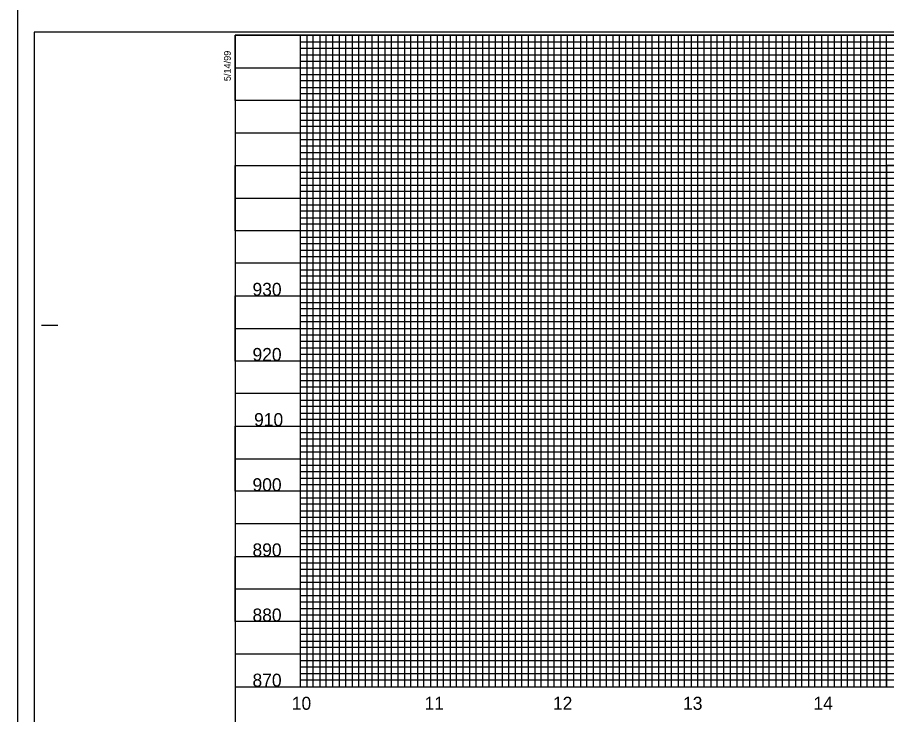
# Model space of a CAD drawing. Extents: x 1967929 to 1975641, y 546296 to 568534.
# Drawn here: x 1969864 to 1970531, y 565787 to 566323 of the extents above; entities that cross this region are included whole.
import ezdxf

# ---------------------------------------------------------------- set-up
doc = ezdxf.new("R2010")
doc.units = 0
for name, color, linetype in [('Exist Vertical Profile Horizontal Axis Label Major', 7, 'Continuous'), ('Exist Vertical Profile Vertical Axis Label', 7, 'Continuous'), ('Old_Level_41', 7, 'Continuous'), ('Scratch_Level_3', 7, 'Continuous'), ('Sheet Cutting Line CELL', 7, 'Continuous'), ('Sheet Plot Border Inside CELL', 7, 'Continuous'), ('Sheet Plot Border Outside CELL', 7, 'Continuous'), ('Sheet Profile CELL', 7, 'Continuous'), ('Sheet Profile Grid Major CELL', 7, 'Continuous'), ('Sheet Profile Grid Middle CELL', 7, 'Continuous'), ('Sheet Profile Grid Minor CELL', 7, 'Continuous')]:
    doc.layers.add(name, color=color, linetype=linetype)

msp = doc.modelspace()

# ---------------------------------------------------------------- linework, layer by layer
at = {"layer": 'Old_Level_41'}
msp.add_line((1969882.95, 566086.36), (1969895.45, 566086.36), dxfattribs=at)
at = {"layer": 'Scratch_Level_3'}
for points in [[(1970031.45, 565808.86), (1970781.45, 565808.86), (1970781.45, 566308.86), (1970031.45, 566308.86)], [(1970081.45, 566308.86), (1970081.45, 565808.86), (1971481.45, 565808.86), (1971481.45, 566112.51), (1971331.4, 566112.51), (1971331.4, 566308.86)], [(1970081.45, 566308.86), (1970081.45, 565808.86), (1971331.45, 565808.86), (1971331.45, 566077.21), (1971331.45, 566077.21), (1971331.45, 566308.86)], [(1970531.45, 566208.86), (1970531.45, 565808.86), (1971931.45, 565808.86), (1971931.45, 566112.51), (1971781.45, 566112.51), (1971781.45, 566208.86)]]:
    msp.add_lwpolyline(points, close=True, dxfattribs=at)
at = {"layer": 'Sheet Cutting Line CELL'}
msp.add_line((1969864.45, 566333.86), (1969864.45, 565233.86), dxfattribs=at)
at = {"layer": 'Sheet Plot Border Inside CELL'}
msp.add_lwpolyline([(1969877.45, 565256.31), (1971543.95, 565256.31), (1971543.95, 566311.41), (1969877.45, 566311.41)], close=True, dxfattribs=at)
at = {"layer": 'Sheet Plot Border Outside CELL'}
msp.add_lwpolyline([(1969864.45, 565233.86), (1971548.45, 565233.86), (1971548.45, 566333.86), (1969864.45, 566333.86)], close=True, dxfattribs=at)
at = {"layer": 'Sheet Profile CELL'}
msp.add_line((1970031.45, 565808.86), (1971531.45, 565808.86), dxfattribs=at)
msp.add_lwpolyline([(1971531.45, 566308.86), (1970031.45, 566308.86), (1970031.45, 565258.86), (1971531.45, 565258.86)], close=True, dxfattribs=at)
at = {"layer": 'Sheet Profile Grid Major CELL'}
for p, q in [((1970031.45, 566158.86), (1970031.45, 566208.86)), ((1970031.45, 566208.86), (1970681.45, 566208.86)), ((1970681.45, 566158.86), (1970031.45, 566158.86)), ((1970031.45, 566058.86), (1970031.45, 566108.86)), ((1970031.45, 566108.86), (1970681.45, 566108.86)), ((1970681.45, 566058.86), (1970031.45, 566058.86)), ((1970031.45, 565958.86), (1970031.45, 566008.86)), ((1970031.45, 566008.86), (1970681.45, 566008.86)), ((1970681.45, 565958.86), (1970031.45, 565958.86)), ((1970031.45, 565858.86), (1970031.45, 565908.86)), ((1970031.45, 565908.86), (1970681.45, 565908.86)), ((1970681.45, 565858.86), (1970031.45, 565858.86))]:
    msp.add_line(p, q, dxfattribs=at)
for points in [[(1970681.45, 566258.86), (1970031.45, 566258.86), (1970031.45, 566308.86), (1971331.45, 566308.86)], [(1970081.45, 566308.86), (1970081.45, 565808.86), (1970131.45, 565808.86), (1970131.45, 566308.86)], [(1970181.45, 566308.86), (1970181.45, 565808.86), (1970231.45, 565808.86), (1970231.45, 566308.86)], [(1970281.45, 566308.86), (1970281.45, 565808.86), (1970331.45, 565808.86), (1970331.45, 566308.86)], [(1970381.45, 566308.86), (1970381.45, 565808.86), (1970431.45, 565808.86), (1970431.45, 566308.86)], [(1970481.45, 566308.86), (1970481.45, 565808.86), (1970531.45, 565808.86), (1970531.45, 566308.86)]]:
    msp.add_lwpolyline(points, dxfattribs=at)
at = {"layer": 'Sheet Profile Grid Middle CELL'}
for p, q in [((1970031.45, 566233.86), (1970031.45, 566183.86)), ((1970681.45, 566233.86), (1970031.45, 566233.86)), ((1970031.45, 566183.86), (1970681.45, 566183.86)), ((1970031.45, 566133.86), (1970031.45, 566083.86)), ((1970681.45, 566133.86), (1970031.45, 566133.86)), ((1970031.45, 566083.86), (1970681.45, 566083.86)), ((1970031.45, 566033.86), (1970031.45, 565983.86)), ((1970681.45, 566033.86), (1970031.45, 566033.86)), ((1970031.45, 565983.86), (1970681.45, 565983.86)), ((1970031.45, 565933.86), (1970031.45, 565883.86)), ((1970681.45, 565933.86), (1970031.45, 565933.86)), ((1970031.45, 565883.86), (1970681.45, 565883.86))]:
    msp.add_line(p, q, dxfattribs=at)
for points in [[(1970031.45, 566308.86), (1970031.45, 566283.86), (1970681.45, 566283.86)], [(1970106.45, 565808.86), (1970106.45, 566308.86)], [(1970156.45, 566308.86), (1970156.45, 565808.86), (1970206.45, 565808.86), (1970206.45, 566308.86)], [(1970256.45, 566308.86), (1970256.45, 565808.86), (1970306.45, 565808.86), (1970306.45, 566308.86)], [(1970356.45, 566308.86), (1970356.45, 565808.86), (1970406.45, 565808.86), (1970406.45, 566308.86)], [(1970456.45, 566308.86), (1970456.45, 565808.86), (1970506.45, 565808.86), (1970506.45, 566308.86)], [(1970681.45, 565833.86), (1970031.45, 565833.86)]]:
    msp.add_lwpolyline(points, dxfattribs=at)
at = {"layer": 'Sheet Profile Grid Minor CELL'}
for p, q in [((1970081.45, 566248.86), (1970081.45, 566243.86)), ((1970681.45, 566248.86), (1970081.45, 566248.86)), ((1970081.45, 566243.86), (1970681.45, 566243.86)), ((1970681.45, 566238.86), (1970081.45, 566238.86)), ((1970081.45, 566238.86), (1970081.45, 566228.86)), ((1970081.45, 566228.86), (1970681.45, 566228.86)), ((1970681.45, 566223.86), (1970081.45, 566223.86)), ((1970081.45, 566223.86), (1970081.45, 566218.86)), ((1970081.45, 566218.86), (1970681.45, 566218.86)), ((1970681.45, 566213.86), (1970081.45, 566213.86)), ((1970081.45, 566213.86), (1970081.45, 566203.86)), ((1970081.45, 566203.86), (1970681.45, 566203.86)), ((1970681.45, 566198.86), (1970081.45, 566198.86)), ((1970081.45, 566198.86), (1970081.45, 566193.86)), ((1970081.45, 566193.86), (1970681.45, 566193.86)), ((1970681.45, 566188.86), (1970081.45, 566188.86)), ((1970081.45, 566188.86), (1970081.45, 566178.86)), ((1970081.45, 566178.86), (1970681.45, 566178.86)), ((1970681.45, 566173.86), (1970081.45, 566173.86)), ((1970081.45, 566173.86), (1970081.45, 566168.86)), ((1970081.45, 566168.86), (1970681.45, 566168.86)), ((1970681.45, 566163.86), (1970081.45, 566163.86)), ((1970081.45, 566163.86), (1970081.45, 566153.86)), ((1970081.45, 566153.86), (1970681.45, 566153.86)), ((1970081.45, 566148.86), (1970081.45, 566143.86)), ((1970681.45, 566148.86), (1970081.45, 566148.86)), ((1970081.45, 566143.86), (1970681.45, 566143.86)), ((1970081.45, 566138.86), (1970081.45, 566128.86)), ((1970681.45, 566138.86), (1970081.45, 566138.86)), ((1970081.45, 566128.86), (1970681.45, 566128.86)), ((1970081.45, 566123.86), (1970081.45, 566118.86)), ((1970681.45, 566123.86), (1970081.45, 566123.86)), ((1970081.45, 566118.86), (1970681.45, 566118.86)), ((1970681.45, 566113.86), (1970081.45, 566113.86)), ((1970081.45, 566113.86), (1970081.45, 566103.86)), ((1970081.45, 566103.86), (1970681.45, 566103.86)), ((1970681.45, 566098.86), (1970081.45, 566098.86)), ((1970081.45, 566098.86), (1970081.45, 566093.86)), ((1970081.45, 566093.86), (1970681.45, 566093.86)), ((1970681.45, 566088.86), (1970081.45, 566088.86)), ((1970081.45, 566088.86), (1970081.45, 566078.86)), ((1970081.45, 566078.86), (1970681.45, 566078.86)), ((1970681.45, 566073.86), (1970081.45, 566073.86)), ((1970081.45, 566073.86), (1970081.45, 566068.86)), ((1970081.45, 566068.86), (1970681.45, 566068.86)), ((1970681.45, 566063.86), (1970081.45, 566063.86)), ((1970081.45, 566063.86), (1970081.45, 566053.86)), ((1970081.45, 566053.86), (1970681.45, 566053.86)), ((1970681.45, 566048.86), (1970081.45, 566048.86)), ((1970081.45, 566048.86), (1970081.45, 566043.86)), ((1970081.45, 566043.86), (1970681.45, 566043.86)), ((1970681.45, 566038.86), (1970081.45, 566038.86)), ((1970081.45, 566038.86), (1970081.45, 566028.86)), ((1970081.45, 566028.86), (1970681.45, 566028.86)), ((1970681.45, 566023.86), (1970081.45, 566023.86)), ((1970081.45, 566023.86), (1970081.45, 566018.86)), ((1970081.45, 566018.86), (1970681.45, 566018.86)), ((1970681.45, 566013.86), (1970081.45, 566013.86)), ((1970081.45, 566003.86), (1970681.45, 566003.86)), ((1970681.45, 565998.86), (1970081.45, 565998.86)), ((1970081.45, 565998.86), (1970081.45, 565993.86)), ((1970081.45, 565993.86), (1970681.45, 565993.86)), ((1970681.45, 565988.86), (1970081.45, 565988.86)), ((1970081.45, 565978.86), (1970681.45, 565978.86)), ((1970681.45, 565973.86), (1970081.45, 565973.86)), ((1970081.45, 565973.86), (1970081.45, 565968.86)), ((1970081.45, 565968.86), (1970681.45, 565968.86)), ((1970681.45, 565963.86), (1970081.45, 565963.86)), ((1970081.45, 565963.86), (1970081.45, 565953.86)), ((1970081.45, 565953.86), (1970681.45, 565953.86)), ((1970681.45, 565948.86), (1970081.45, 565948.86)), ((1970081.45, 565948.86), (1970081.45, 565943.86)), ((1970081.45, 565943.86), (1970681.45, 565943.86)), ((1970681.45, 565938.86), (1970081.45, 565938.86)), ((1970081.45, 565938.86), (1970081.45, 565928.86)), ((1970081.45, 565928.86), (1970681.45, 565928.86)), ((1970681.45, 565923.86), (1970081.45, 565923.86)), ((1970081.45, 565923.86), (1970081.45, 565918.86)), ((1970081.45, 565918.86), (1970681.45, 565918.86)), ((1970681.45, 565913.86), (1970081.45, 565913.86)), ((1970081.45, 565913.86), (1970081.45, 565903.86)), ((1970081.45, 565903.86), (1970681.45, 565903.86)), ((1970681.45, 565898.86), (1970081.45, 565898.86)), ((1970081.45, 565898.86), (1970081.45, 565893.86)), ((1970081.45, 565893.86), (1970681.45, 565893.86)), ((1970681.45, 565888.86), (1970081.45, 565888.86)), ((1970081.45, 565888.86), (1970081.45, 565878.86)), ((1970081.45, 565878.86), (1970681.45, 565878.86)), ((1970081.45, 565873.86), (1970081.45, 565868.86)), ((1970681.45, 565873.86), (1970081.45, 565873.86)), ((1970081.45, 565868.86), (1970681.45, 565868.86)), ((1970681.45, 565863.86), (1970081.45, 565863.86)), ((1970081.45, 565863.86), (1970081.45, 565853.86)), ((1970081.45, 565853.86), (1970681.45, 565853.86)), ((1970681.45, 565848.86), (1970081.45, 565848.86)), ((1970081.45, 565848.86), (1970081.45, 565843.86)), ((1970081.45, 565843.86), (1970681.45, 565843.86)), ((1970681.45, 565838.86), (1970081.45, 565838.86)), ((1970081.45, 565838.86), (1970081.45, 565828.86)), ((1970081.45, 565828.86), (1970681.45, 565828.86)), ((1970081.45, 565823.86), (1970081.45, 565818.86)), ((1970681.45, 565823.86), (1970081.45, 565823.86)), ((1970081.45, 565818.86), (1970681.45, 565818.86)), ((1970681.45, 565813.86), (1970081.45, 565813.86)), ((1970081.45, 565813.86), (1970081.45, 565808.86)), ((1970081.45, 565808.86), (1971481.45, 565808.86))]:
    msp.add_line(p, q, dxfattribs=at)
for points in [[(1970081.45, 566303.86), (1970681.45, 566303.86)], [(1970086.45, 566308.86), (1970086.45, 565808.86), (1970091.45, 565808.86), (1970091.45, 566308.86)], [(1970096.45, 566308.86), (1970096.45, 565808.86), (1970101.45, 565808.86), (1970101.45, 566308.86)], [(1970111.45, 566308.86), (1970111.45, 565808.86), (1970116.45, 565808.86), (1970116.45, 566308.86)], [(1970121.45, 566308.86), (1970121.45, 565808.86), (1970126.45, 565808.86), (1970126.45, 566308.86)], [(1970136.45, 566308.86), (1970136.45, 565808.86), (1970141.45, 565808.86), (1970141.45, 566308.86)], [(1970146.45, 566308.86), (1970146.45, 565808.86), (1970151.45, 565808.86), (1970151.45, 566308.86)], [(1970161.45, 566308.86), (1970161.45, 565808.86), (1970166.45, 565808.86), (1970166.45, 566308.86)], [(1970171.45, 566308.86), (1970171.45, 565808.86), (1970176.45, 565808.86), (1970176.45, 566308.86)], [(1970186.45, 566308.86), (1970186.45, 565808.86), (1970191.45, 565808.86), (1970191.45, 566308.86)], [(1970196.45, 566308.86), (1970196.45, 565808.86), (1970201.45, 565808.86), (1970201.45, 566308.86)], [(1970211.45, 566308.86), (1970211.45, 565808.86), (1970216.45, 565808.86), (1970216.45, 566308.86)], [(1970221.45, 566308.86), (1970221.45, 565808.86), (1970226.45, 565808.86), (1970226.45, 566308.86)], [(1970236.45, 566308.86), (1970236.45, 565808.86), (1970241.45, 565808.86), (1970241.45, 566308.86)], [(1970246.45, 565808.86), (1970251.45, 565808.86), (1970251.45, 566308.86)], [(1970246.45, 566308.86), (1970246.45, 565808.86)], [(1970261.45, 566308.86), (1970261.45, 565808.86), (1970266.45, 565808.86), (1970266.45, 566308.86)], [(1970271.45, 566308.86), (1970271.45, 565808.86), (1970276.45, 565808.86), (1970276.45, 566308.86)], [(1970286.45, 566308.86), (1970286.45, 565808.86), (1970291.45, 565808.86), (1970291.45, 566308.86)], [(1970296.45, 566308.86), (1970296.45, 565808.86), (1970301.45, 565808.86), (1970301.45, 566308.86)], [(1970311.45, 566308.86), (1970311.45, 565808.86), (1970316.45, 565808.86), (1970316.45, 566308.86)], [(1970321.45, 566308.86), (1970321.45, 565808.86), (1970326.45, 565808.86), (1970326.45, 566308.86)], [(1970336.45, 566308.86), (1970336.45, 565808.86), (1970341.45, 565808.86), (1970341.45, 566308.86)], [(1970346.45, 566308.86), (1970346.45, 565808.86), (1970351.45, 565808.86), (1970351.45, 566308.86)], [(1970361.45, 566308.86), (1970361.45, 565808.86), (1970366.45, 565808.86), (1970366.45, 566308.86)], [(1970371.45, 566308.86), (1970371.45, 565808.86), (1970376.45, 565808.86), (1970376.45, 566308.86)], [(1970386.45, 566308.86), (1970386.45, 565808.86), (1970391.45, 565808.86), (1970391.45, 566308.86)], [(1970396.45, 566308.86), (1970396.45, 565808.86), (1970401.45, 565808.86), (1970401.45, 566308.86)], [(1970411.45, 566308.86), (1970411.45, 565808.86), (1970426.45, 565808.86), (1970426.45, 566308.86)], [(1970416.45, 566308.86), (1970416.45, 565808.86), (1970421.45, 565808.86), (1970421.45, 566308.86)], [(1970436.45, 566308.86), (1970436.45, 565808.86), (1970441.45, 565808.86), (1970441.45, 566308.86)], [(1970446.45, 566308.86), (1970446.45, 565808.86), (1970451.45, 565808.86), (1970451.45, 566308.86)], [(1970461.45, 566308.86), (1970461.45, 565808.86), (1970466.45, 565808.86), (1970466.45, 566308.86)], [(1970471.45, 566308.86), (1970471.45, 565808.86), (1970476.45, 565808.86), (1970476.45, 566308.86)], [(1970486.45, 566308.86), (1970486.45, 565808.86), (1970491.45, 565808.86), (1970491.45, 566308.86)], [(1970496.45, 566308.86), (1970496.45, 565808.86), (1970501.45, 565808.86), (1970501.45, 566308.86)], [(1970511.45, 566308.86), (1970511.45, 565808.86), (1970516.45, 565808.86), (1970516.45, 566308.86)], [(1970521.45, 566308.86), (1970521.45, 565808.86), (1970526.45, 565808.86), (1970526.45, 566308.86)], [(1970681.45, 566298.86), (1970081.45, 566298.86), (1970081.45, 566293.86), (1970681.45, 566293.86)], [(1970681.45, 566288.86), (1970081.45, 566288.86), (1970081.45, 566278.86), (1970681.45, 566278.86)], [(1970681.45, 566273.86), (1970081.45, 566273.86), (1970081.45, 566268.86), (1970681.45, 566268.86)], [(1970681.45, 566263.86), (1970081.45, 566263.86), (1970081.45, 566253.86), (1970681.45, 566253.86)]]:
    msp.add_lwpolyline(points, dxfattribs=at)

# ---------------------------------------------------------------- texts
at = {"layer": 'Exist Vertical Profile Horizontal Axis Label Major'}
for s, p in [('10', (1970075.03, 565791.11)), ('11', (1970176.87, 565791.11)), ('12', (1970275.42, 565791.11)), ('13', (1970375.26, 565791.11)), ('14', (1970475.31, 565791.11))]:
    msp.add_text(s, height=10, dxfattribs=at).set_placement(p)
at = {"layer": 'Exist Vertical Profile Vertical Axis Label'}
for s, p in [('930', (1970044.88, 566108.86)), ('920', (1970044.88, 566058.86)), ('910', (1970046.08, 566008.86)), ('900', (1970044.88, 565958.86)), ('890', (1970044.88, 565908.86)), ('880', (1970044.88, 565858.86)), ('870', (1970044.88, 565808.86))]:
    msp.add_text(s, height=10, dxfattribs=at).set_placement(p)
at = {"layer": 'Sheet Profile CELL'}
msp.add_text('5/14/99', height=5.25, rotation=90, dxfattribs=at).set_placement((1970028.2, 566273.66))

doc.saveas('drawing.dxf')
